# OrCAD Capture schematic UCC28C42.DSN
size Custom; title: UCC28C42 BiCMOS Low-Power Current Mode PWM; rev: 1.0; note: DS:slus458d EVM: slua274a
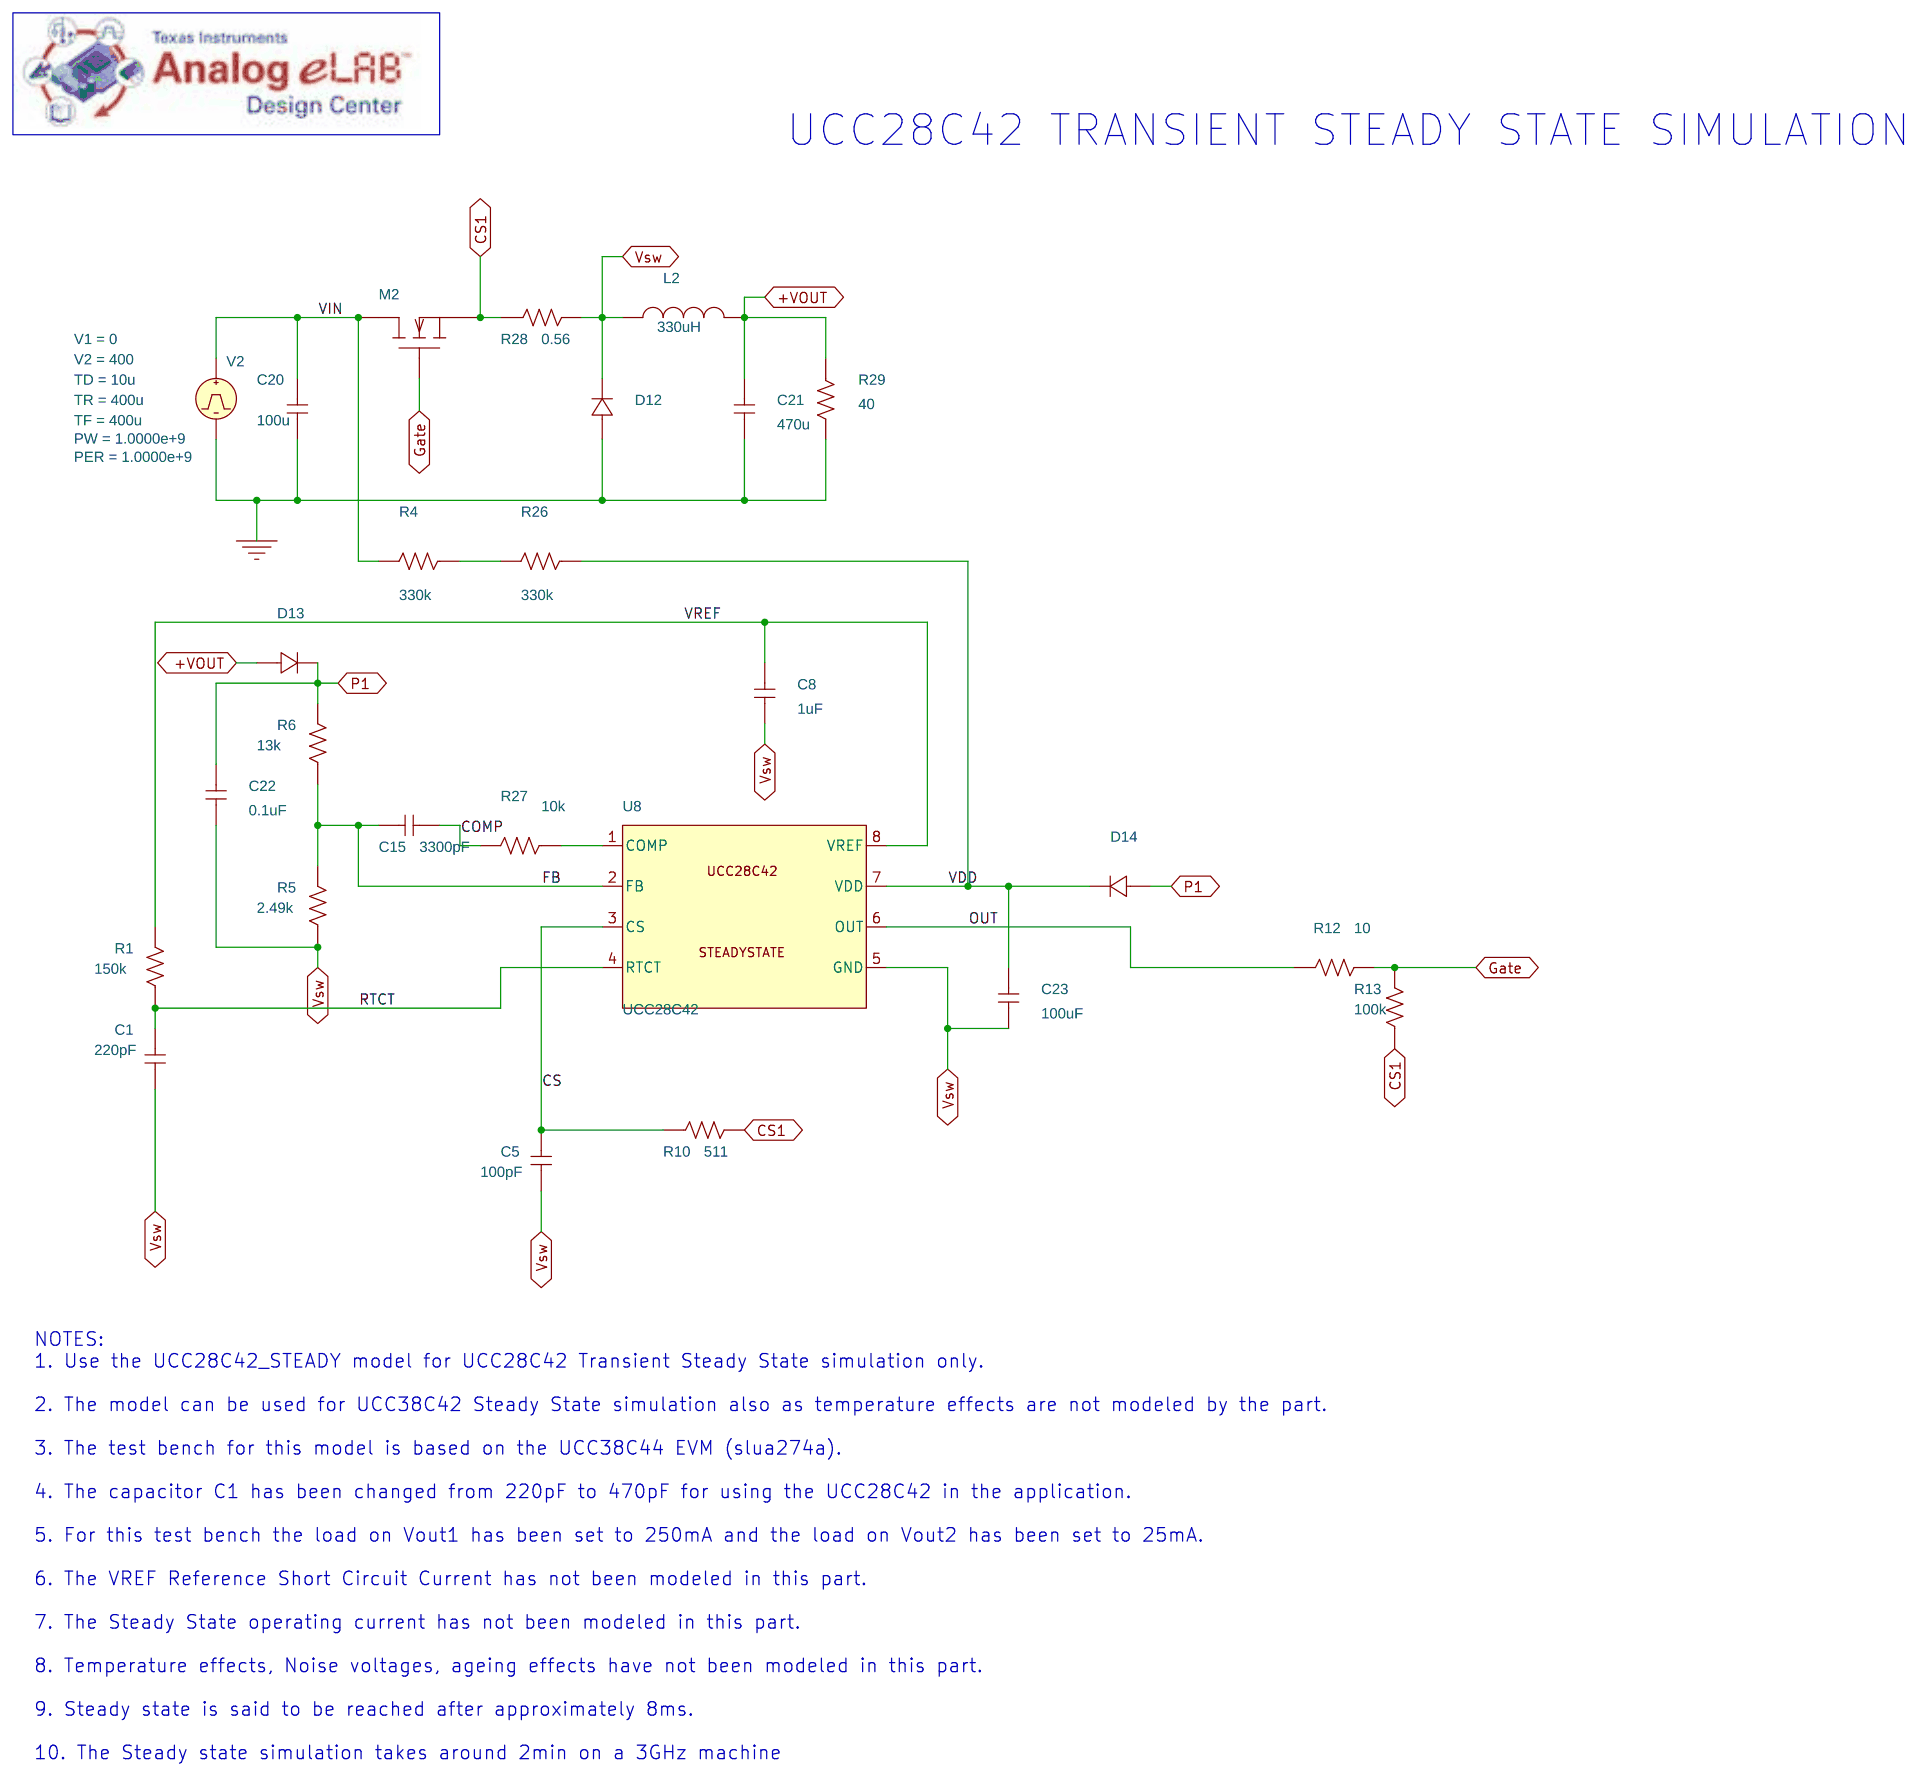
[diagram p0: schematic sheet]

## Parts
C1  220pF  [CK05]
C5  100pF  [CK05]
C8  1uF  [CK05]
C15  3300pF  [CK05]
C20  100u  [RAD/CK05]
C21  470u  [RAD/CK05]
C22  0.1uF  [CK05]
C23  100uF  [CK05]
D12  POWER_DIODE_P
D13  POWER_DIODE_P
D14  POWER_DIODE_P
L2  330uH  [DISC/.350x.175/LS.200x.100/.034]
M2  POWER_NMOS_P
R1  150k  [RC05]
R4  330k  [RC05]
R5  2.49k  [RC05]
R6  13k  [RC05]
R10  511  [RC05]
R12  10  [RC05]
R13  100k  [RC05]
R26  330k  [RC05]
R27  10k  [RC05]
R28  0.56  [RC05]
R29  40  [RC05]
U8  UCC28C42
V2  VPULSE

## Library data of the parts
C1 C5 C8 C15 C22 C23 = C
C20 = C: AppProp: InductiveSlave:;SRF:;PrevCap:100u;PrevESL:
C21 = C: AppProp: InductiveSlave:;SRF:;PrevCap:470u;PrevESL:
D12-D14 = POWER_DIODE_P: CT_ZERO_VOLTS: 300p; I_REV_LEAK: 1e-5; VJ_KNEE: 0.9
L2 = L: AppProp: SRF:; IC: 0; RDC: 0.1; Tolerance: 1
M2 = POWER_NMOS_P: BVDSS: 1000.0; CISS: 1170p; COSS: 136p; CRSS: 58p; IDSS: 1u; QG: 17.2n; TRR: 50n
R1 R4-R6 R10 R12 R13 R26-R29 = R
U8 = UCC28C42_STEADY
V2 = VPULSE: AC: 0; AppProp: Pulse$Voltage$0$-1; DC: 400; PER: 1.0000e+9; PW: 1.0000e+9; TD: 10u; TF: 400u; TR: 400u; V1: 0; V2: 400

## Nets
VDD: C23.1 D14.1(2) R26.1 U8.7(VDD)
VIN: C20.2 M2.2(d) R4.2 V2.1(+)
0: C20.1 C21.1 D12.0(1) R29.2 V2.2(-)
+VOUT: C21.2 D13.0(1) L2.2 R29.1
COMP: C15.1 R27.2
CS: C5.1 R10.1 U8.3(CS)
CS1: M2.0(s) R10.2 R13.1 R28.1
FB: C15.2 R5.2 R6.1 U8.2(FB)
Gate: M2.1(g) R12.2 R13.2
OUT: R12.1 U8.6(OUT)
P1: C22.1 D13.1(2) D14.0(1) R6.2
RTCT: C1.1 R1.1 U8.4(RTCT)
VREF: C8.1 R1.2 U8.8(VREF)
Vsw: C1.2 C5.2 C8.2 C22.2 C23.2 D12.1(2) L2.1 R5.1 R28.2 U8.5(GND)
N16777826: R4.1 R26.2
N16777958: R27.1 U8.1(COMP)

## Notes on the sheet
- UCC28C42 TRANSIENT STEADY STATE SIMULATION
- NOTES:
  1. Use the UCC28C42_STEADY model for UCC28C42 Transient Steady State simulation only.
  2. The model can be used for UCC38C42 Steady State simulation also as temperature effects are not modeled by the part.
  3. The test bench for this model is based on the UCC38C44 EVM (slua274a).
  4. The capacitor C1 has been changed from 220pF to 470pF for using the UCC28C42 in the application.
  5. For this test bench the load on Vout1 has been set to 250mA and the load on Vout2 has been set to 25mA.
  6. The VREF Reference Short Circuit Current has not been modeled in this part.
  7. The Steady State operating current has not been modeled in this part.
  8. Temperature effects, Noise voltages, ageing effects have not been modeled in this part.
  9. Steady state is said to be reached after approximately 8ms.
  10. The Steady state simulation takes around 2min on a 3GHz machine
